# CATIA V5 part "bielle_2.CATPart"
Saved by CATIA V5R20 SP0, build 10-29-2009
Part number: sqlt_bielle_2
Publications: "longueur_bielle_2", "rayon_pivot_bielle", "épaisseur_piece", "distance_angle_droit", "longueur_T", "Plan.1", "Point.1", "Droite.1", "Point.2", "Point.4", "Point.6", "Droite.2", "Droite.3", "Plan.2", "Point.7", "Droite.4", "Point.8", "Droite.5", "Point.9", "Point.10", "Point.11", "Point.12"
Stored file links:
  D:\ecole\thinkmotion\IAO\bielle_2.CATPart
  D:\ecole\thinkmotion\IAO\bielle_1.CATPart
  D:\ecole\thinkmotion\IAO\sqlt mecanisme coulisseau.CATProduct
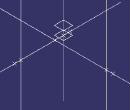
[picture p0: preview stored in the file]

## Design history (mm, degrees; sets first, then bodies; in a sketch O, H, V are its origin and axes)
Parameters
  longueur_bielle_2 = 100 mm {= External.longueur_bielle_2}
  rayon_pivot_bielle = 5 mm {= External.rayon_pivot_bielle}
  `épaisseur_piece` = 20 mm {= `External.épaisseur_piece`}
  distance_angle_droit = 20 mm {= External.distance_angle_droit}
  longueur_T = 120 mm {= External.longueur_T}
  `largeur_bielle-rayon_pivot` = 10 mm {= External.largeur_bielle_2 -External.rayon_pivot_bielle}
External parameters (linked from other documents)
  External.longueur_bielle_2 = 100 mm
  External.rayon_pivot_bielle = 5 mm
  `External.épaisseur_piece` = 20 mm
  External.distance_angle_droit = 20 mm
  External.longueur_T = 120 mm
  External.largeur_bielle_2 = 15 mm
Set1 "sqlt_bielle_2"
  Plane1: type Offset, RefPlane xy-plane, Offset 0
  Point1: (0, 0, 0)
  Line1: type PtDir, RefPoint Point1, Direction yz-plane, Start 0, End 20
  Point2: type OnCurve, Support Line1, Length 100 {= longueur_bielle_2}
  Line2: type PtDir, RefPoint Point1, Direction Plane1, Start 0, End 20
  Line3: type PtDir, RefPoint Point2, Direction Plane1, Start 0, End 20
  Plane2: type Offset, RefPlane xy-plane, Offset 20 {= `épaisseur_piece`}
  Point3: type OnCurve, Support Line1, Length 20 {= distance_angle_droit}
  Line4: type PtDir, RefPoint Point3, Direction zx-plane, Start 0, End 20
  Point4: type OnCurve, Support Line4, Length 120 {= longueur_T}
  Line5: type PtDir, RefPoint Point4, Direction Plane2, Start 0, End 20
  Point5: (0, 15 {= `largeur_bielle-rayon_pivot` +rayon_pivot_bielle}, 0), relative to Point4
  Point6: (15 {= `largeur_bielle-rayon_pivot` +rayon_pivot_bielle}, 0, 0), relative to Point2
  Point7: (-15 {= -`largeur_bielle-rayon_pivot` -rayon_pivot_bielle}, 0, 0)
Body1 (main body)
